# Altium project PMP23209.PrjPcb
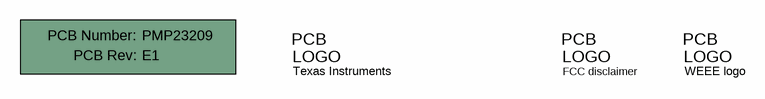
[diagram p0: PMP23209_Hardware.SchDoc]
CopyrightYear: 2021; PCB_Layout: John Gomez; PCB_Rev: E1; PRJ_Customer: Texas Instruments; PRJ_Engineer: John Gomez; PRJ_Number: PMP23209; PRJ_Title: Isolated Bias Supply for PMP22650 with Reinforced Transformer Insulation; SCH_Rev: E1; TechSupport: http://www.ti.com/support; TID: N/A
2 sheets, 29 parts. Net scope: global (net labels, ports and power ports of the same name join across sheets).
Board file: PMP23209.PcbDoc
Sheets:
  PMP23209_Hardware.SchDoc
  PMP23209_sheet1.SchDoc

## Sheet PMP23209_Hardware.SchDoc
size 431 x 279 mm; Date: Not shown in title block; ApprovedBy: Not shown in title block; CheckedBy: Not shown in title block; Author: Not shown in title block; CompanyName: Not shown in title block; Engineer: Not shown in title block; Organization: Not shown in title block; Address1: Not shown in title block; Address2: Not shown in title block; Address3: Not shown in title block; Address4: Not shown in title block; DocumentNumber: 3; Revision: Use project parameter SCH_Rev; SheetNumber: 3; SheetTotal: 3; PageSetup: Record=PageOptions¦CenterHorizontal=True¦CenterVertical=True¦PrintScale=1.00¦XCorrection=1.00¦YCorrection=1.00¦PrintKind=0¦BorderSize=5000000¦LeftOffset=0¦BottomOffset=0¦Orientation=2¦PaperLength=1000¦PaperWidth=1000¦Scale=100¦PaperSource=15¦PrintQuality=600¦MediaType=1¦DitherType=10¦PaperKind=Letter¦PrintScaleMode=1

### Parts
!PCB1  Printed Circuit Board  (value not drawn)  (mechanical)
Logo1  Texas Instruments  [TI_Symbol_Overlay_Small]  (no BOM)
Logo2  FCC disclaimer  [FCC_disclaimer]  (no BOM)
Logo3  WEEE logo  [WEEE_Minimum]  (no BOM)

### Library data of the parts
!PCB1 = CMP-0003618-2: Manufacturer: Any; PartNumber: PMP23209
Logo1 = CMP-0074838-1: Texas Instrument Corporate Signature; SymbolCreator: a0412235; Lib Reference: TI_Logo; Library Reference: Logo
Logo2 = CMP-0074847-1: FCC_disclaimer; Library Reference: Logo
Logo3 = CMP-0074769-1

## Sheet PMP23209_sheet1.SchDoc
size A2; DocumentNumber: 2; SheetNumber: 2; SheetTotal: 2; PageSetup: Record=PageOptions¦CenterHorizontal=True¦CenterVertical=True¦PrintScale=0.69¦XCorrection=1.00¦YCorrection=1.00¦PrintKind=0¦BorderSize=5000000¦LeftOffset=0¦BottomOffset=0¦Orientation=2¦PaperLength=1000¦PaperWidth=1000¦Scale=100¦PaperSource=15¦PrintQuality=600¦MediaType=1¦DitherType=10¦PaperKind=Letter¦PrintScaleMode=1
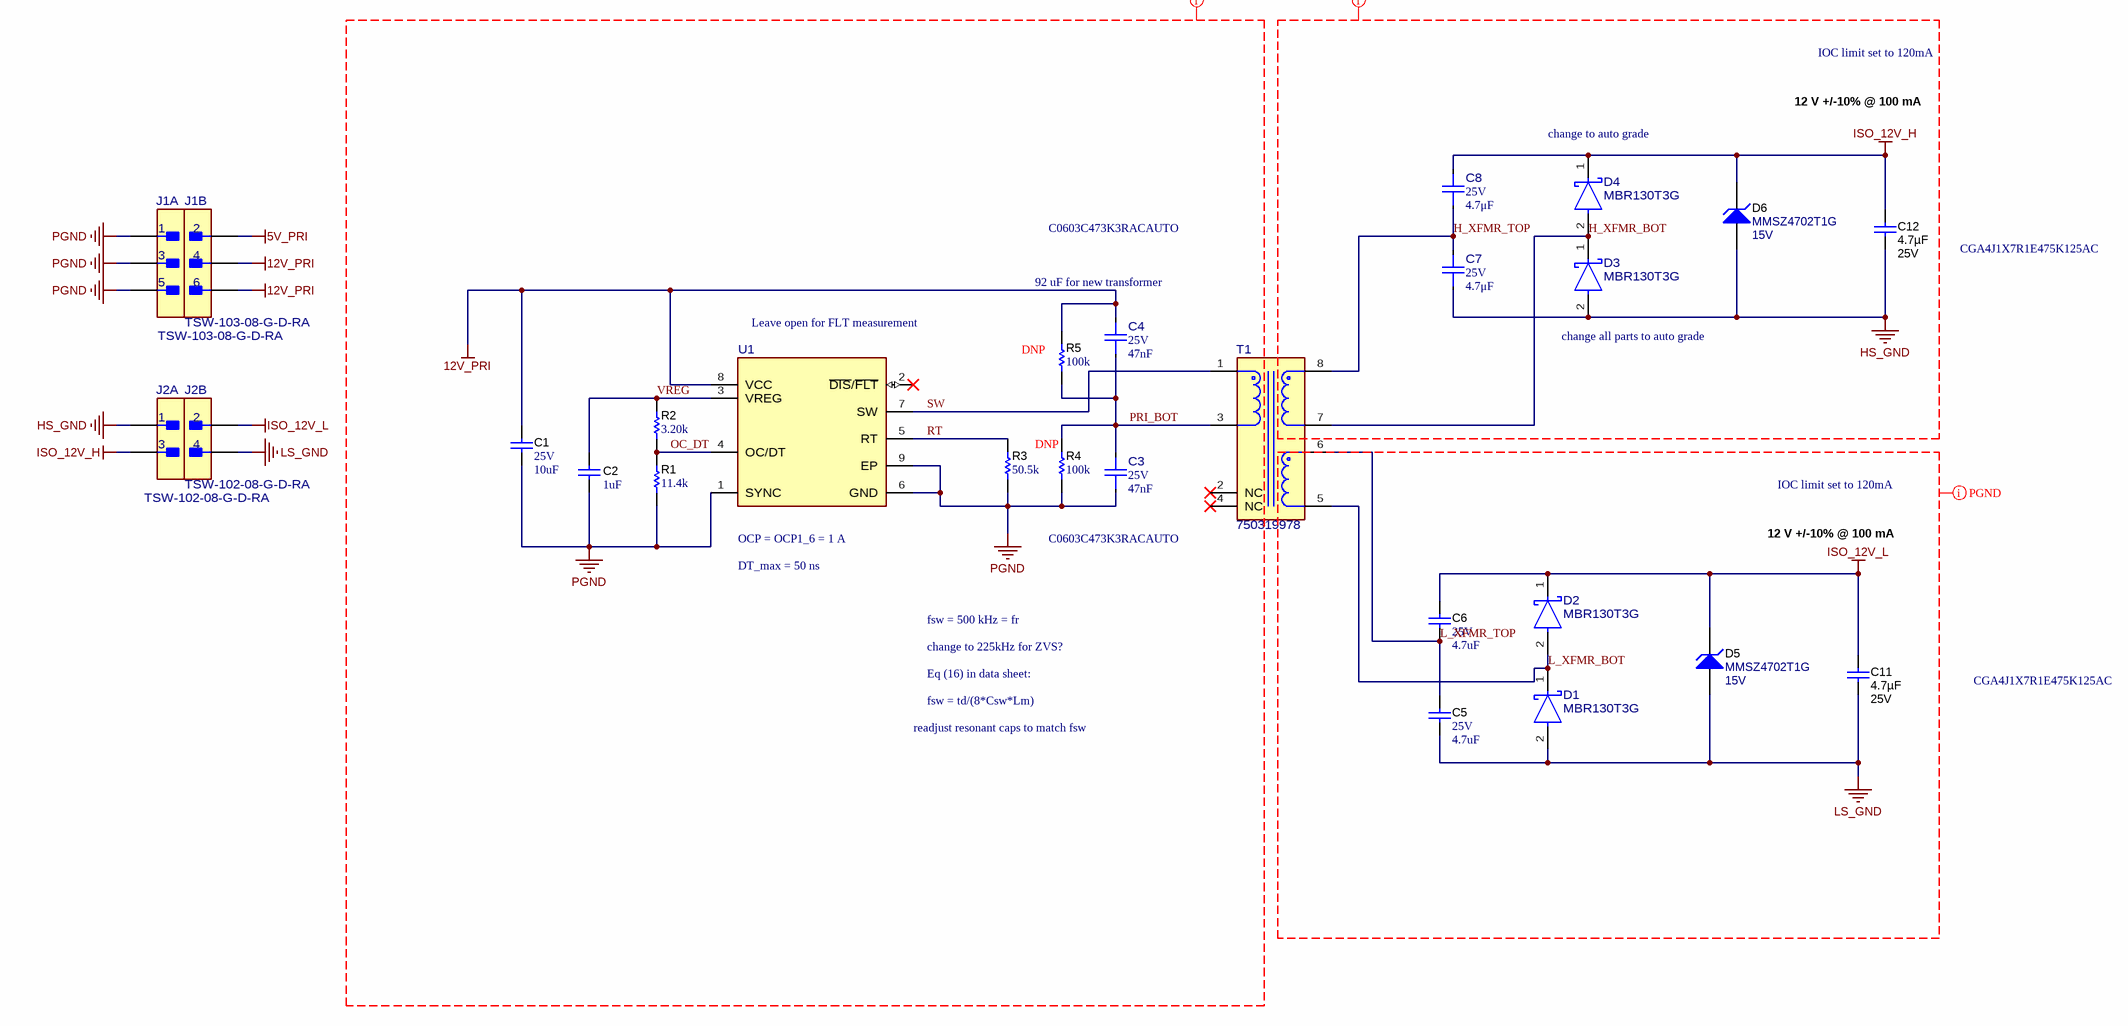
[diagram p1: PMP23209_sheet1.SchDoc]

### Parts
C1  VDC_V: 25V  ValueDisplayed: 10uF  [0805_HV]  (hidden comment: GRM219R61E106KA12D)
C2  ValueDisplayed: 1uF  [0603]  (hidden comment: GRM185R61A105KE36D)
C3  VDC_V: 25V  ValueDisplayed: 47nF  [FP-C1608X8R1E683M080AA_0603-MFG]  (hidden comment: C1608X8R1E683M080AA)
C4  VDC_V: 25V  ValueDisplayed: 47nF  [FP-C1608X8R1E683M080AA_0603-MFG]  (hidden comment: C1608X8R1E683M080AA)
C5  VDC_V: 25V  ValueDisplayed: 4.7uF  [0603]  (hidden comment: GRM188R61E475KE11D)
C6  VDC_V: 25V  ValueDisplayed: 4.7uF  [0603]  (hidden comment: GRM188R61E475KE11D)
C7  VDC_V: 25V  ValueDisplayed: 4.7μF  [FP-C1608X5R1E475M080AC_0603-MFG]  (hidden comment: C1608X5R1E475M080AC)
C8  VDC_V: 25V  ValueDisplayed: 4.7μF  [FP-C1608X5R1E475M080AC_0603-MFG]  (hidden comment: C1608X5R1E475M080AC)
C11  Cap_F: 4.7µF  VDC_V: 25V  [0805_HV]  (hidden comment: GRM21BR71E475KA73L)
C12  Cap_F: 4.7µF  VDC_V: 25V  [0805_HV]  (hidden comment: GRM21BR71E475KA73L)
D1  MBR130T3G  [FP-MBR130T3G_SOD123-MFG]
D2  MBR130T3G  [FP-MBR130T3G_SOD123-MFG]
D3  MBR130T3G  [FP-MBR130T3G_SOD123-MFG]
D4  MBR130T3G  [FP-MBR130T3G_SOD123-MFG]
D5  MMSZ4702T1G  value 15V  [SOD-123]
D6  MMSZ4702T1G  value 15V  [SOD-123]
J1  TSW-103-08-G-D-RA  [FP-TSW-103-08-G-D-RA_HDR6-MFG]  (parts A,B of 2)
J2  TSW-102-08-G-D-RA  [FP-TSW-102-08-G-D-RA_HDR4-MFG]  (parts A,B of 2)
R1  ValueDisplayed: 11.4k  [0603]  (hidden comment: RT0603DRE0711K4L)
R2  ValueDisplayed: 3.20k  [0603]  (hidden comment: RT0603BRD073K2L)
R3  ValueDisplayed: 50.5k  [0603]  (hidden comment: RT0603DRE0750K5L)
R4  ValueDisplayed: 100k  [0603]  (hidden comment: RT0603BRD073K2L)
R5  ValueDisplayed: 100k  [0603]  (hidden comment: RT0603BRD073K2L)
T1  750319978  [FP-750319978_SMT_XFRMR_9MM54_10MM26-MFG]
U1  UCC25800DGNRQ1  [DGN0008G-MFG]  (value not drawn)

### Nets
5V_PRI: J1.2
12V_PRI: C1.1 C4.2 J1.4 J1.6 R5.2 U1.8(VCC)
HS_GND: C7.1 C12.2 D3.2(ANODE) D6.2(A) J2.1
ISO_12V_H: C8.2 C12.1 D4.1(CATHODE) D6.1(K) J2.3
ISO_12V_L: C6.1 C11.1 D2.1(CATHODE) D5.1(K) J2.2
LS_GND: C5.2 C11.2 D1.2(ANODE) D5.2(A) J2.4
PGND: C1.2 C2.2 C3.1 J1.1 J1.3 J1.5 R1.1 R3.1 R4.1 U1.1(SYNC) U1.6(GND) U1.9(EP)
H_XFMR_BOT: D3.1(CATHODE) D4.2(ANODE) T1.7
H_XFMR_TOP: C7.2 C8.1 T1.8
L_XFMR_BOT: D1.1(CATHODE) D2.2(ANODE) T1.5
L_XFMR_TOP: C5.1 C6.2 T1.6
OC_DT: R1.2 R2.1 U1.4(OC/DT)
PRI_BOT: C3.2 C4.1 R4.2 R5.1 T1.3
RT: R3.2 U1.5(RT)
SW: T1.1 U1.7(SW)
VREG: C2.1 R2.2 U1.3(VREG)

Not connected (* = marked no-connect by the designer): T1 2(NC)* 4(NC)*; U1 2(~{DIS}/~{FLT})*

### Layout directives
net class INGND: 12V_PRI, OC_DT, PGND, PRI_BOT, RT, SW, VREG
net class VSWNET: H_XFMR_BOT, H_XFMR_TOP, HS_GND, ISO_12V_H
net class PGND: ISO_12V_L, L_XFMR_BOT, L_XFMR_TOP, LS_GND

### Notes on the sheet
- IOC limit set to 120mA
- 12 V +/-10% @ 100 mA
- (near D4) change to auto grade
- C0603C473K3RACAUTO
- CGA4J1X7R1E475K125AC
- Leave open for FLT measurement
- 92 uF for new transformer
- (near R5) DNP
- (near D3) change all parts to auto grade
- (near R4) DNP
- (near U1) OCP = OCP1_6 = 1 A
- DT_max = 50 ns
- fsw = 500 kHz = fr
- change to 225kHz for ZVS?
- readjust resonant caps to match fsw
- Eq (16) in data sheet:
- fsw = td/(8*Csw*Lm)

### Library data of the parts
C1 = CMP-0008206-2: CAP, CERM, 10 uF, 25 V, +/- 10%, X5R, 0805; Manufacturer: MuRata; TaMin_C: -55°C; Polarized: N; SizeAreaWB_mm2: 6.75; Value1: Unknown; U/M: EA; Value: 10uF; TaMax_C: 85°C; SizeZ_mm: 1.45; SizeX_mm: 2; SizeY_mm: 1.25; Cap_Case: 0805; SizeArea_mm2: 2.5; Cap_F: 10µF; AEC Category: Q200
C2 = CMP-0007156-4: CAP, CERM, 1 uF, 10 V, +/- 10%, X5R, 0603; Manufacturer: MuRata; TaMin_C: -55°C; Polarized: N; SizeAreaWB_mm2: 4.68; Value1: Unknown; U/M: EA; Value: 1uF; TaMax_C: 85°C; SizeZ_mm: 1; SizeX_mm: 1.6; SizeY_mm: 0.8; Value2: 10V; SizeArea_mm2: 1.28; Cap_F: 1µF; AEC Category: Q200
C3 C4 = CMP-0094554-1: Multilayer Ceramic Capacitors 68nF ±20% 25V X8R SMD 0603; Manufacturer: TDK; TempCo: 0.15; AEC Qualified: No; Tolerance_%: 0.2%; Voltage: 50V; SizeZ_mm: 0.9mm
C5 C6 = CMP-0007347-4: CAP, CERM, 4.7 uF, 25 V, +/- 10%, X5R, 0603; Manufacturer: MuRata; TaMin_C: -55°C; Polarized: N; SizeAreaWB_mm2: 4.68; Value1: Unknown; U/M: EA; Value: 4.7uF; TaMax_C: 85°C; SizeZ_mm: 1; SizeX_mm: 1.6; SizeY_mm: 0.8; SizeArea_mm2: 1.28; Cap_F: 4.7µF; AEC Category: Q200
C7 C8 = CMP-0094553-1: Multilayer Ceramic Capacitors 4.7μF ±20% 25V X5R SMD 0603; Manufacturer: TDK; Tolerance_%: 0.2%; Voltage: 50V; TempCo: 0.15; SizeZ_mm: 0.9mm; AEC Qualified: No
C11 C12 = CMP-0008346-2: CAP, CERM, 4.7 uF, 25 V, +/- 10%, X7R, 0805; Manufacturer: MuRata; TaMin_C: -55°C; Polarized: N; SizeAreaWB_mm2: 6.75; Value1: Unknown; U/M: EA; Value: 4.7uF; TaMax_C: 125°C; SizeZ_mm: 1.45; SizeX_mm: 2; SizeY_mm: 1.25; Cap_Case: 0805; SizeArea_mm2: 2.5; AEC Category: Q200
D1-D4 = CMP-0094495-1: Diode Schottky 30 V 1A Surface Mount SOD-123; Manufacturer: onsemi; Import Ts: 1521868375; Standoff Height: 0mm; Vr_V: 30V; SizeZ_mm: 1.35mm; Peak Reverse Current: 60uA; TJmax_C: 125°C; Ciiva Ids: 822455; Max Surge Forward Current: 5.5A; AEC Qualified: No
D5 D6 = CMP-0005745-1: Diode, Zener, 15 V, 500 mW, SOD-123; Manufacturer: ON Semiconductor; Power_W: 500mW; SizeAreaWB_mm2: 13.095; Value1: 0.5W; RJA_CperW: 340; U/M: EA; SizeZ_mm: 1.35; SizeX_mm: 3.85; SizeY_mm: 1.7; SizeArea_mm2: 6.545; AEC Category: Q101
J1 = CMP-0090622-1: Connector Header Through Hole, Right Angle 6 position 0.100" (2.54mm); Manufacturer: Samtec; ContactFinish: Gold,Nickel; Current_A: 5.7A; Is Female: no; SizeZ_mm: 5.69mm; Voltage_V: 550V; Row_Count: 2; Conn Gender: Male
J2 = CMP-0088304-1: CONN HEADER R/A 4POS 2.54MM; Manufacturer: Samtec; SizeZ_mm: 5.69mm; Row_Count: 2; ContactFinish: Gold,Tin; AEC Qualified: No; Conn Gender: Male; Conn Orientation: Right Angle
R1 = CMP-0024611-1: RES, 11.4 k, 0.5%, 0.1 W, 0603; Manufacturer: Yageo America; Power_W: 100mW; TempCo: 50 ppm/C; Value_Code: 11k4; U/M: EA; Value: 11.4k; EIA_Code: E192; SizeX_mm: 1.6; SizeY_mm: 0.8; SizeZ_mm: 1; Value2: 0.1W; SizeArea_mm2: 1.28; VDC_V: 75V; AEC Category: Q200
R2 R4 R5 = CMP-0024193-2: RES, 3.20 k, 0.1%, 0.1 W, 0603; Manufacturer: Yageo America; Power_W: 100mW; TempCo: 25 ppm/C; Value_Code: 3k20; U/M: EA; Value: 3.20k; EIA_Code: E192; Res_ohm: 3.2k; SizeX_mm: 1.6; SizeY_mm: 0.8; SizeZ_mm: 1; Value2: 0.1W; SizeArea_mm2: 1.28; VDC_V: 75V; AEC Category: Q200
R3 = CMP-0025375-2: RES, 50.5 k, 0.5%, 0.1 W, 0603; Manufacturer: Yageo America; Power_W: 100mW; TempCo: 50 ppm/C; Value_Code: 50k5; U/M: EA; Value: 50.5k; EIA_Code: E192; SizeX_mm: 1.6; SizeY_mm: 0.8; SizeZ_mm: 1; Value2: 0.1W; SizeArea_mm2: 1.28; VDC_V: 75V; AEC Category: Q200
T1 = CMP-0094831-1: Transformer, 1:1.11:1.11, 0.065Ohm PRI, 0.07Ohm SEC, 141uH, 9.54x10.26x5.38mm, SMT; Manufacturer: Wurth Electronics; Ind_H: 141µH; AEC Qualified: No; SizeZ_mm: 5.38mm; ValueDisplayed: 6.6pF; DCR_ohm: 0.065; Rsec1_ohm: 0.07
U1 = CMP-0088494-2: Open Loop LLC Transformer Driver for Isolated Bias Supplies; Manufacturer: Texas Instruments; Min Supply Voltage: 12V; SizeZ_mm: 1.1mm; Number Of Outputs: 1; Standoff Height: 0.05mm; AEC Category: Q200; Max Duty Cycle: 50%; TaMin_C: -40°C; TJmax_C: +150°C; AEC Qualified: No; Switching Frequency: 100-2000kHz; CompType: IC; Max Supply Voltage: 36V; TaMax_C: +125°C; Output Type: Other; Nominal Supply Current: 500uA

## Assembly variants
001: not fitted R4 R5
